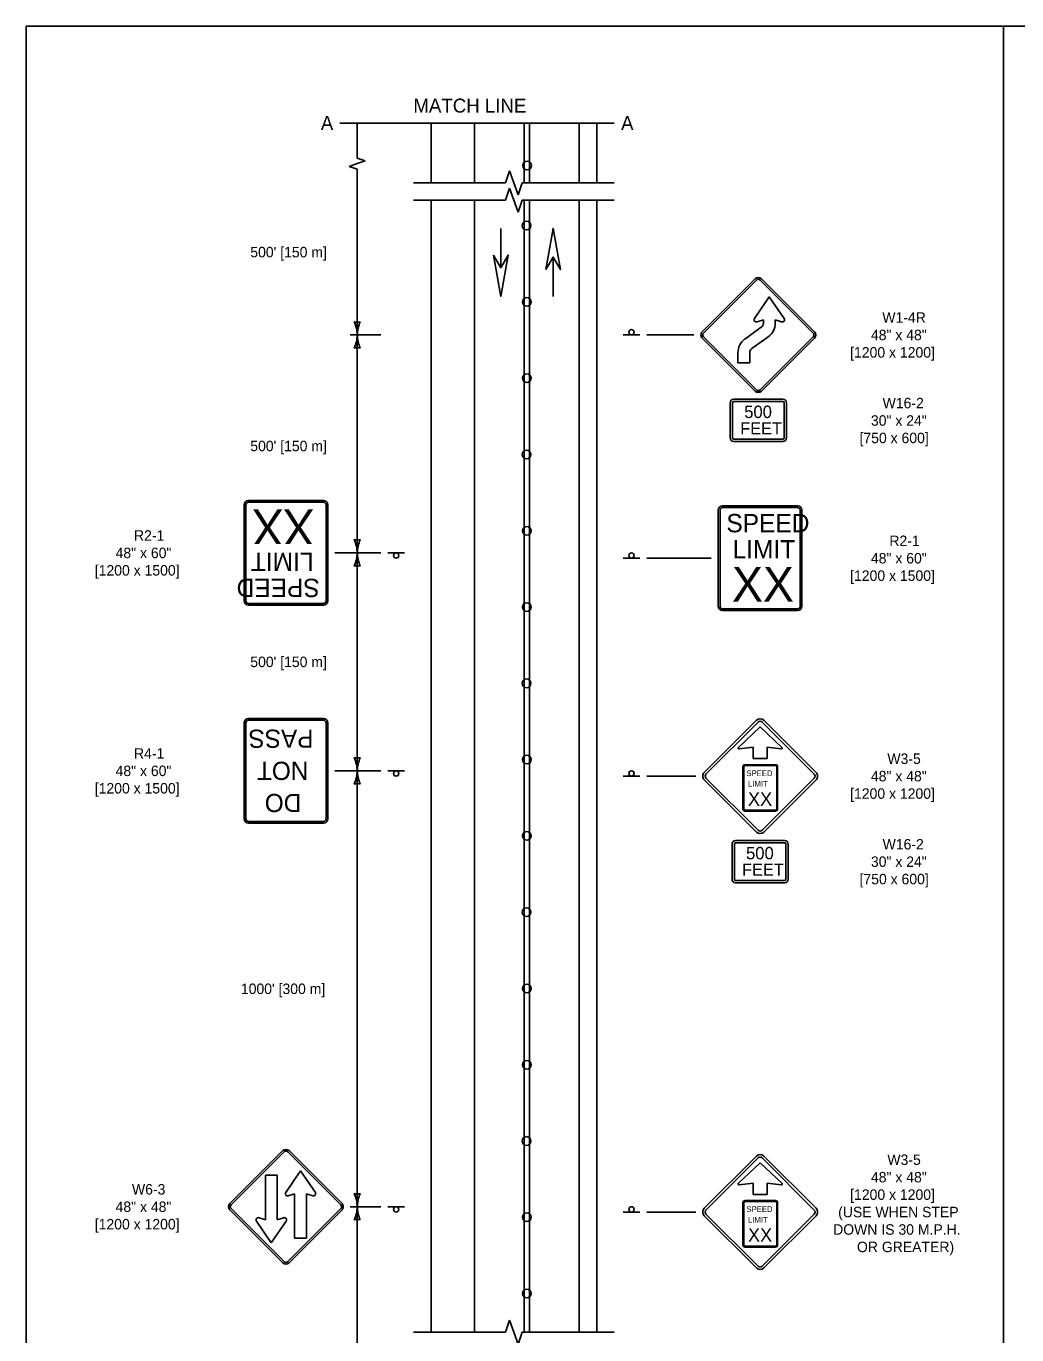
# Model space of a CAD drawing. Extents: x 49991.4 to 50021, y 49987.6 to 50011.4.
# Drawn here: x 49999.38 to 50005.06, y 49991.49 to 49999 of the extents above; entities that cross this region are included whole.
import ezdxf

# ---------------------------------------------------------------- set-up
doc = ezdxf.new("R2010")
doc.units = 0
for name, color, linetype in [('Level 1', 7, 'Continuous'), ('Level 2', 7, 'Continuous'), ('Level 3', 7, 'Continuous'), ('Level 6', 7, 'Continuous')]:
    doc.layers.add(name, color=color, linetype=linetype)

msp = doc.modelspace()

# ---------------------------------------------------------------- linework, layer by layer
at = {"layer": 'Level 1'}
for p, q in [((50001.7052, 49998.1012), (50001.7052, 49998.4436)), ((50001.9552, 49998.1012), (50001.9552, 49998.4436)), ((50002.2402, 49998.1012), (50002.2402, 49998.4436)), ((50002.2702, 49998.1012), (50002.2702, 49998.4436)), ((50002.5552, 49998.1012), (50002.5552, 49998.4436)), ((50002.6552, 49998.1012), (50002.6552, 49998.4436)), ((50001.7052, 49991.5092), (50001.7052, 49998.0012)), ((50001.9552, 49991.5092), (50001.9552, 49998.0012)), ((50002.2402, 49991.5092), (50002.2402, 49998.0012)), ((50002.2702, 49991.5092), (50002.2702, 49998.0012)), ((50002.5552, 49991.5092), (50002.5552, 49998.0012)), ((50002.6552, 49991.5092), (50002.6552, 49998.0012)), ((50002.1052, 49997.8396), (50002.1052, 49997.6138)), ((50002.1054, 49997.8396), (50002.1054, 49997.6138)), ((50002.4051, 49997.4496), (50002.4051, 49997.6754)), ((50002.4053, 49997.4496), (50002.4053, 49997.6754)), ((50003.2604, 49997.2459), (50003.5645, 49997.5499)), ((50003.2675, 49997.2388), (50003.5715, 49997.5429)), ((50003.5927, 49997.5429), (50003.8968, 49997.2388)), ((50003.5998, 49997.5499), (50003.9039, 49997.2459)), ((50003.6452, 49997.4466), (50003.5602, 49997.3229)), ((50003.7304, 49997.3229), (50003.6452, 49997.4466)), ((50003.5748, 49997.3032), (50003.6113, 49997.315)), ((50003.6113, 49997.315), (50003.6113, 49997.2962)), ((50003.6792, 49997.2962), (50003.6792, 49997.315)), ((50003.6792, 49997.315), (50003.7157, 49997.3032)), ((50002.8071, 49997.2283), (50002.9031, 49997.2283)), ((50003.5992, 49997.2725), (50003.5056, 49997.205)), ((50003.5645, 49996.9065), (50003.2604, 49997.2105)), ((50003.5715, 49996.9135), (50003.2675, 49997.2176)), ((50003.5453, 49997.1498), (50003.6389, 49997.2174)), ((50003.8968, 49997.2176), (50003.5927, 49996.9135)), ((50003.9039, 49997.2105), (50003.5998, 49996.9065)), ((50003.4653, 49997.1263), (50003.4653, 49997.068)), ((50003.5332, 49997.068), (50003.5332, 49997.1263)), ((50003.4653, 49997.068), (50003.5332, 49997.068)), ((50003.441, 49996.8592), (50003.7233, 49996.8592)), ((50003.4209, 49996.6375), (50003.4209, 49996.8391)), ((50003.4343, 49996.8391), (50003.4343, 49996.6375)), ((50003.7233, 49996.8458), (50003.441, 49996.8458)), ((50003.73, 49996.6375), (50003.73, 49996.8391)), ((50003.7434, 49996.8391), (50003.7434, 49996.6375)), ((50003.441, 49996.6308), (50003.7233, 49996.6308)), ((50003.7233, 49996.6173), (50003.441, 49996.6173)), ((50000.6331, 49995.7033), (50000.6331, 49996.2533)), ((50000.6431, 49995.7033), (50000.6431, 49996.2533)), ((50000.6581, 49996.2783), (50001.0881, 49996.2783)), ((50000.6581, 49996.2683), (50001.0881, 49996.2683)), ((50001.1031, 49996.2533), (50001.1031, 49995.7033)), ((50001.1131, 49996.2533), (50001.1131, 49995.7033)), ((50003.3527, 49995.6728), (50003.3527, 49996.2228)), ((50003.3627, 49995.6728), (50003.3627, 49996.2228)), ((50003.3777, 49996.2478), (50003.8077, 49996.2478)), ((50003.3777, 49996.2378), (50003.8077, 49996.2378)), ((50003.8227, 49996.2228), (50003.8227, 49995.6728)), ((50003.8327, 49996.2228), (50003.8327, 49995.6728)), ((50001.5532, 49995.9783), (50001.4572, 49995.9783)), ((50002.8071, 49995.9478), (50002.9031, 49995.9478)), ((50001.0881, 49995.6883), (50000.6581, 49995.6883)), ((50001.0881, 49995.6783), (50000.6581, 49995.6783)), ((50003.8077, 49995.6578), (50003.3777, 49995.6578)), ((50003.8077, 49995.6478), (50003.3777, 49995.6478)), ((50000.6331, 49994.4533), (50000.6331, 49995.0033)), ((50000.6431, 49994.4533), (50000.6431, 49995.0033)), ((50000.6581, 49995.0281), (50001.0881, 49995.0281)), ((50000.6581, 49995.0181), (50001.0881, 49995.0181)), ((50001.1031, 49995.0033), (50001.1031, 49994.4533)), ((50001.1131, 49995.0033), (50001.1131, 49994.4533)), ((50003.272, 49994.7192), (50003.5713, 49995.0185)), ((50003.2821, 49994.7091), (50003.5814, 49995.0084)), ((50003.4683, 49994.8628), (50003.5927, 49994.9801)), ((50003.5927, 49994.9801), (50003.7171, 49994.8628)), ((50003.604, 49995.0084), (50003.9033, 49994.7091)), ((50003.604, 49995.0084), (50003.604, 49995.0084)), ((50003.6141, 49995.0185), (50003.9134, 49994.7192)), ((50003.6141, 49995.0185), (50003.6141, 49995.0185)), ((50003.5524, 49994.8642), (50003.4724, 49994.8541)), ((50003.5524, 49994.7987), (50003.5524, 49994.8642)), ((50003.633, 49994.8642), (50003.633, 49994.7987)), ((50003.7131, 49994.8541), (50003.633, 49994.8642)), ((50003.4934, 49994.7511), (50003.4934, 49994.5098)), ((50003.4986, 49994.7511), (50003.4986, 49994.5098)), ((50003.6806, 49994.7636), (50003.5059, 49994.7636)), ((50003.6806, 49994.7584), (50003.5059, 49994.7584)), ((50003.633, 49994.7987), (50003.5524, 49994.7987)), ((50003.5932, 49994.7636), (50003.5932, 49994.7636)), ((50003.6879, 49994.5098), (50003.6879, 49994.7511)), ((50003.6931, 49994.5098), (50003.6931, 49994.7511)), ((50001.5532, 49994.7283), (50001.4572, 49994.7283)), ((50002.8071, 49994.6979), (50002.9031, 49994.6979)), ((50003.5713, 49994.3772), (50003.272, 49994.6765)), ((50003.5814, 49994.3873), (50003.2821, 49994.6866)), ((50003.9033, 49994.6866), (50003.604, 49994.3873)), ((50003.9134, 49994.6765), (50003.6141, 49994.3772)), ((50003.5059, 49994.5025), (50003.6806, 49994.5025)), ((50003.5059, 49994.4973), (50003.6806, 49994.4973)), ((50001.0881, 49994.4381), (50000.6581, 49994.4381)), ((50001.0881, 49994.4281), (50000.6581, 49994.4281)), ((50003.4314, 49994.1066), (50003.4314, 49994.3082)), ((50003.4449, 49994.3082), (50003.4449, 49994.1066)), ((50003.4516, 49994.3283), (50003.7338, 49994.3283)), ((50003.7338, 49994.3149), (50003.4516, 49994.3149)), ((50003.7406, 49994.1066), (50003.7406, 49994.3082)), ((50003.754, 49994.3082), (50003.754, 49994.1066)), ((50003.4516, 49994.0998), (50003.7338, 49994.0998)), ((50003.7338, 49994.0864), (50003.4516, 49994.0864)), ((50000.5513, 49992.2459), (50000.8555, 49992.5499)), ((50000.5585, 49992.2387), (50000.8625, 49992.5429)), ((50000.8837, 49992.5429), (50001.1877, 49992.2387)), ((50000.8909, 49992.5499), (50001.1949, 49992.2459)), ((50003.272, 49992.2192), (50003.5713, 49992.5185)), ((50003.2821, 49992.2091), (50003.5814, 49992.5084)), ((50003.604, 49992.5084), (50003.9033, 49992.2091)), ((50003.604, 49992.5084), (50003.604, 49992.5084)), ((50003.6141, 49992.5185), (50003.9134, 49992.2192)), ((50003.6141, 49992.5185), (50003.6141, 49992.5185)), ((50000.8717, 49992.3107), (50000.9569, 49992.4345)), ((50000.9569, 49992.4345), (50001.0421, 49992.3107)), ((50003.4683, 49992.3628), (50003.5927, 49992.4801)), ((50003.5927, 49992.4801), (50003.7171, 49992.3628)), ((50000.7553, 49992.4089), (50000.8233, 49992.4089)), ((50000.7553, 49992.1535), (50000.7553, 49992.4089)), ((50000.8233, 49992.4089), (50000.8233, 49992.1535)), ((50003.5524, 49992.3641), (50003.4724, 49992.3541)), ((50003.5524, 49992.2986), (50003.5524, 49992.3641)), ((50003.633, 49992.3641), (50003.633, 49992.2986)), ((50003.7131, 49992.3541), (50003.633, 49992.3641)), ((50000.9229, 49992.3031), (50000.8865, 49992.2911)), ((50000.9229, 49992.0475), (50000.9229, 49992.3031)), ((50001.0273, 49992.2911), (50000.9909, 49992.3031)), ((50000.9909, 49992.3031), (50000.9909, 49992.0475)), ((50003.633, 49992.2986), (50003.5524, 49992.2986)), ((50000.8555, 49991.9065), (50000.5513, 49992.2105)), ((50000.8625, 49991.9135), (50000.5585, 49992.2175)), ((50001.1877, 49992.2175), (50000.8837, 49991.9135)), ((50001.1949, 49992.2105), (50000.8909, 49991.9065)), ((50001.5532, 49992.2283), (50001.4572, 49992.2283)), ((50003.4934, 49992.2511), (50003.4934, 49992.0098)), ((50003.4986, 49992.2511), (50003.4986, 49992.0098)), ((50003.6806, 49992.2635), (50003.5059, 49992.2635)), ((50003.6806, 49992.2583), (50003.5059, 49992.2583)), ((50003.5932, 49992.2635), (50003.5932, 49992.2635)), ((50003.6879, 49992.0098), (50003.6879, 49992.2511)), ((50003.6931, 49992.0098), (50003.6931, 49992.2511)), ((50000.7893, 49992.0219), (50000.7043, 49992.1455)), ((50000.7189, 49992.1651), (50000.7553, 49992.1535)), ((50000.8745, 49992.1455), (50000.7893, 49992.0219)), ((50000.8233, 49992.1535), (50000.8597, 49992.1651)), ((50002.8071, 49992.1978), (50002.9031, 49992.1978)), ((50003.5713, 49991.8771), (50003.272, 49992.1764)), ((50003.5814, 49991.8872), (50003.2821, 49992.1865)), ((50003.9033, 49992.1865), (50003.604, 49991.8872)), ((50003.9134, 49992.1764), (50003.6141, 49991.8771)), ((50000.9909, 49992.0475), (50000.9229, 49992.0475)), ((50003.5059, 49992.0025), (50003.6806, 49992.0025)), ((50003.5059, 49991.9973), (50003.6806, 49991.9973))]:
    msp.add_line(p, q, dxfattribs=at)
for points in [[(49999.3835, 49998.9992), (50016.7501, 49998.9992), (50016.7501, 49987.7988), (49999.3835, 49987.7988)], [(50002.3633, 49997.6032), (50002.4051, 49997.8396), (50002.4469, 49997.6032), (50002.4051, 49997.6752)], [(50002.0634, 49997.686), (50002.1052, 49997.4496), (50002.147, 49997.686), (50002.1052, 49997.614)]]:
    msp.add_lwpolyline(points, close=True, dxfattribs=at)
for centre, radius in [((50002.2561, 49998.1995), 0.025), ((50002.2524, 49997.8552), 0.025), ((50002.255, 49997.4177), 0.025), ((50002.855, 49997.2436), 0.0152), ((50002.255, 49996.9802), 0.025), ((50002.255, 49996.9802), 0.025), ((50002.2524, 49996.5427), 0.025), ((50002.255, 49996.1052), 0.025), ((50001.5052, 49995.9631), 0.0152), ((50002.855, 49995.9631), 0.0152), ((50002.255, 49995.6677), 0.025), ((50002.255, 49995.6677), 0.025), ((50002.2524, 49995.2302), 0.025), ((50002.255, 49994.7927), 0.025), ((50001.5052, 49994.7131), 0.0152), ((50002.855, 49994.7132), 0.0152), ((50002.255, 49994.3552), 0.025), ((50002.255, 49994.3552), 0.025), ((50002.2524, 49993.9177), 0.025), ((50002.255, 49993.4802), 0.025), ((50002.255, 49993.0427), 0.025), ((50002.255, 49993.0427), 0.025), ((50002.2524, 49992.6052), 0.025), ((50001.5052, 49992.2131), 0.0152), ((50002.855, 49992.2131), 0.0152), ((50002.255, 49992.1677), 0.025), ((50002.255, 49991.7302), 0.025)]:
    msp.add_circle(centre, radius, dxfattribs=at)
for centre, radius, start, end in [((50003.5821, 49997.5324), 0.025, 45, 135), ((50003.5821, 49997.5324), 0.015, 45, 135), ((50003.5708, 49997.3157), 0.0129, 145.48059, 287.95818), ((50003.7197, 49997.3157), 0.0129, 252.04182, 34.51941), ((50003.2781, 49997.2283), 0.025, 134.99976, 225), ((50003.2781, 49997.2283), 0.015, 134.99976, 225), ((50003.5821, 49997.2962), 0.0291, 305.79716, 0), ((50003.5821, 49997.2962), 0.0971, 305.79716, 0), ((50003.8862, 49997.2283), 0.015, 315, 45), ((50003.8862, 49997.2283), 0.025, 315, 45), ((50003.5623, 49997.1264), 0.0971, 125.79716, 180), ((50003.5623, 49997.1264), 0.0291, 125.79744, 180), ((50003.441, 49996.8391), 0.0202, 90, 180), ((50003.5821, 49996.9242), 0.025, 225.00043, 315), ((50003.5821, 49996.9242), 0.015, 225.00043, 315), ((50003.7233, 49996.8391), 0.0202, 0, 90), ((50003.441, 49996.8391), 0.00672, 90, 180), ((50003.7233, 49996.8391), 0.00672, 0, 90), ((50003.441, 49996.6375), 0.0202, 180, 270), ((50003.441, 49996.6375), 0.00672, 180, 270), ((50003.7233, 49996.6375), 0.00672, 270, 0), ((50003.7233, 49996.6375), 0.0202, 270, 0), ((50000.6581, 49996.2533), 0.025, 90, 180), ((50000.6581, 49996.2533), 0.015, 90, 180), ((50001.0881, 49996.2533), 0.025, 0, 90), ((50001.0881, 49996.2533), 0.015, 0, 90), ((50003.3777, 49996.2228), 0.025, 90, 180), ((50003.3777, 49996.2228), 0.015, 90, 180), ((50003.8077, 49996.2228), 0.025, 0, 90), ((50003.8077, 49996.2228), 0.015, 0, 90), ((50000.6581, 49995.7033), 0.025, 180, 270), ((50000.6581, 49995.7033), 0.015, 180, 270), ((50001.0881, 49995.7033), 0.025, 270, 0), ((50001.0881, 49995.7033), 0.015, 270, 0), ((50003.3777, 49995.6728), 0.025, 180, 270), ((50003.3777, 49995.6728), 0.015, 180, 270), ((50003.8077, 49995.6728), 0.025, 270, 0), ((50003.8077, 49995.6728), 0.015, 270, 0), ((50000.6581, 49995.0033), 0.025, 90, 180), ((50000.6581, 49995.0033), 0.015, 90, 180), ((50001.0881, 49995.0033), 0.025, 0, 90), ((50001.0881, 49995.0033), 0.015, 0, 90), ((50003.5927, 49994.9972), 0.0302, 45.00007, 134.99993), ((50003.5927, 49994.9972), 0.016, 45.00007, 134.99993), ((50003.4719, 49994.8592), 0.00509, 134.83509, 275.61741), ((50003.7136, 49994.8592), 0.00508, 264.17053, 45.37126), ((50003.5059, 49994.7511), 0.0125, 90, 180), ((50003.5059, 49994.7511), 0.00728, 90, 180), ((50003.6806, 49994.7511), 0.0125, 0, 90), ((50003.6806, 49994.7511), 0.00728, 0, 90), ((50003.2934, 49994.6979), 0.0302, 134.99992, 225.00007), ((50003.2934, 49994.6979), 0.016, 134.99993, 225.00007), ((50003.892, 49994.6979), 0.016, 314.99992, 45.00007), ((50003.892, 49994.6979), 0.0302, 314.99992, 45.00007), ((50000.6581, 49994.4533), 0.025, 180, 270), ((50000.6581, 49994.4533), 0.015, 180, 270), ((50001.0881, 49994.4533), 0.025, 270, 0), ((50001.0881, 49994.4533), 0.015, 270, 0), ((50003.5059, 49994.5098), 0.0125, 180, 270), ((50003.5059, 49994.5098), 0.00728, 180, 270), ((50003.6806, 49994.5098), 0.00728, 270, 0), ((50003.6806, 49994.5098), 0.0125, 270, 0), ((50003.5927, 49994.3986), 0.0302, 225.00007, 314.99993), ((50003.5927, 49994.3986), 0.016, 225.00007, 314.99993), ((50003.4516, 49994.3082), 0.0202, 90, 180), ((50003.4516, 49994.3082), 0.00672, 90, 180), ((50003.7338, 49994.3082), 0.0202, 0, 90), ((50003.7338, 49994.3082), 0.00672, 0, 90), ((50003.4516, 49994.1066), 0.0202, 180, 270), ((50003.4516, 49994.1066), 0.00672, 180, 270), ((50003.7338, 49994.1066), 0.00672, 270, 0), ((50003.7338, 49994.1066), 0.0202, 270, 0), ((50000.8731, 49992.5324), 0.025, 45.00043, 135), ((50000.8731, 49992.5324), 0.015, 45.00043, 135), ((50003.5927, 49992.4971), 0.0302, 45.00007, 134.99993), ((50003.5927, 49992.4971), 0.016, 45.00007, 134.99993), ((50003.4719, 49992.3591), 0.00509, 134.83509, 275.61741), ((50003.7136, 49992.3591), 0.00508, 264.17053, 45.37126), ((50000.8825, 49992.3036), 0.0129, 145.58495, 216.71634), ((50000.8825, 49992.3036), 0.0129, 216.71939, 287.95818), ((50001.0313, 49992.3036), 0.0129, 252.04182, 323.27756), ((50001.0313, 49992.3036), 0.0129, 323.28061, 34.51941), ((50000.5691, 49992.2283), 0.025, 135, 225), ((50000.5691, 49992.2283), 0.015, 135, 225), ((50001.1772, 49992.2283), 0.015, 314.99976, 45), ((50001.1772, 49992.2283), 0.025, 314.99976, 45), ((50003.2934, 49992.1978), 0.0302, 134.99992, 225.00007), ((50003.2934, 49992.1978), 0.016, 134.99993, 225.00007), ((50003.5059, 49992.2511), 0.0125, 90, 180), ((50003.5059, 49992.2511), 0.00728, 90, 180), ((50003.6806, 49992.2511), 0.0125, 0, 90), ((50003.6806, 49992.2511), 0.00728, 0, 90), ((50003.892, 49992.1978), 0.016, 314.99992, 45.00007), ((50003.892, 49992.1978), 0.0302, 314.99992, 45.00007), ((50000.7149, 49992.153), 0.0129, 143.28061, 214.51941), ((50000.7149, 49992.153), 0.0129, 72.04182, 143.27756), ((50000.8638, 49992.153), 0.0129, 36.71939, 107.95818), ((50000.8638, 49992.153), 0.0129, 325.58495, 36.71634), ((50003.5059, 49992.0098), 0.0125, 180, 270), ((50003.5059, 49992.0098), 0.00728, 180, 270), ((50003.6806, 49992.0098), 0.00728, 270, 0), ((50003.6806, 49992.0098), 0.0125, 270, 0), ((50000.8731, 49991.9242), 0.025, 225, 315), ((50000.8731, 49991.9242), 0.015, 225, 315), ((50003.5927, 49991.8985), 0.0302, 225.00007, 314.99993), ((50003.5927, 49991.8985), 0.016, 225.00007, 314.99993)]:
    msp.add_arc(centre, radius, start, end, dxfattribs=at)
at = {"layer": 'Level 3'}
for p, q in [((50004.9877, 49987.7988), (50004.9877, 49998.9992)), ((50001.2822, 49998.2431), (50001.2822, 49998.4436)), ((50001.2365, 49998.1945), (50001.2822, 49998.2107)), ((50001.2822, 49998.2431), (50001.3279, 49998.2269)), ((50001.2822, 49998.2107), (50001.3279, 49998.2269)), ((50001.2365, 49998.1945), (50001.2822, 49998.1783)), ((50001.2822, 49998.1783), (50001.2822, 49997.2283)), ((50001.2422, 49997.2283), (50001.4172, 49997.2283)), ((50001.2822, 49997.2283), (50001.2822, 49995.9546)), ((50003.2131, 49997.2283), (50002.9431, 49997.2283)), ((50001.1531, 49995.9783), (50001.4172, 49995.9783)), ((50001.2822, 49994.7283), (50001.2822, 49995.9783)), ((50003.3127, 49995.9478), (50002.9431, 49995.9478)), ((50001.1531, 49994.7283), (50001.4172, 49994.7283)), ((50001.2822, 49992.2283), (50001.2822, 49994.7283)), ((50003.2232, 49994.6979), (50002.9431, 49994.6979)), ((50001.2422, 49992.2283), (50001.4172, 49992.2283)), ((50001.2822, 49992.2283), (50001.2822, 49991.3619)), ((50002.9431, 49992.1978), (50003.2232, 49992.1978))]:
    msp.add_line(p, q, dxfattribs=at)
for centre, radius, start, end in [((50001.2822, 49997.3565), 0.0548, 252.13882, 287.86118), ((50001.0495, 49997.2168), 0.233, 2.82731, 22.07716), ((50001.5043, 49997.2191), 0.2223, 157.45601, 177.63952), ((50001.0601, 49997.2375), 0.2223, 337.45601, 357.63952), ((50001.5149, 49997.2398), 0.233, 182.82731, 202.07716), ((50001.2822, 49997.1001), 0.0548, 72.13882, 107.86118), ((50001.2822, 49996.1065), 0.0548, 252.13882, 287.86118), ((50001.0495, 49995.9668), 0.233, 2.82731, 22.07716), ((50001.5043, 49995.9691), 0.2223, 157.45601, 177.63952), ((50001.0601, 49995.9875), 0.2223, 337.45601, 357.63952), ((50001.5149, 49995.9898), 0.233, 182.82731, 202.07716), ((50001.2822, 49995.8501), 0.0548, 72.13882, 107.86118), ((50001.2822, 49994.8565), 0.0548, 252.13882, 287.86118), ((50001.0495, 49994.7168), 0.233, 2.82731, 22.07716), ((50001.5043, 49994.7191), 0.2223, 157.45601, 177.63952), ((50001.0601, 49994.7375), 0.2223, 337.45601, 357.63952), ((50001.5149, 49994.7398), 0.233, 182.82731, 202.07716), ((50001.2822, 49994.6001), 0.0548, 72.13882, 107.86118), ((50001.2822, 49992.3565), 0.0548, 252.13882, 287.86118), ((50001.0495, 49992.2168), 0.233, 2.82731, 22.07716), ((50001.5043, 49992.2191), 0.2223, 157.45601, 177.63952), ((50001.0601, 49992.2375), 0.2223, 337.45601, 357.63952), ((50001.5149, 49992.2398), 0.233, 182.82731, 202.07716), ((50001.2822, 49992.1001), 0.0548, 72.13882, 107.86118)]:
    msp.add_arc(centre, radius, start, end, dxfattribs=at)
at = {"layer": 'Level 6'}
for p, q in [((50002.7552, 49998.4436), (50001.1822, 49998.4436)), ((50002.1316, 49998.1012), (50002.156, 49998.17)), ((50002.1802, 49998.1012), (50002.156, 49998.17)), ((50002.1316, 49998.1012), (50001.6052, 49998.1012)), ((50002.1316, 49998.0012), (50002.156, 49998.07)), ((50002.1802, 49998.0012), (50002.156, 49998.07)), ((50002.2044, 49998.0328), (50002.1802, 49998.1012)), ((50002.2044, 49998.0328), (50002.2288, 49998.1012)), ((50002.7552, 49998.1012), (50002.2288, 49998.1012)), ((50002.1316, 49998.0012), (50001.6052, 49998.0012)), ((50002.2044, 49997.9328), (50002.1802, 49998.0012)), ((50002.2044, 49997.9328), (50002.2288, 49998.0012)), ((50002.7552, 49998.0012), (50002.2288, 49998.0012)), ((50002.1316, 49991.5092), (50002.156, 49991.578)), ((50002.1802, 49991.5092), (50002.156, 49991.578)), ((50002.1316, 49991.5092), (50001.6052, 49991.5092)), ((50002.2044, 49991.4408), (50002.1802, 49991.5092)), ((50002.2044, 49991.4408), (50002.2288, 49991.5092)), ((50002.7552, 49991.5092), (50002.2288, 49991.5092))]:
    msp.add_line(p, q, dxfattribs=at)

# ---------------------------------------------------------------- texts
at = {"layer": 'Level 1'}
for s, height, rotation, p in [('500', 0.07124, 360, (50003.5012, 49996.7517)), ('FEET', 0.06989, 360, (50003.4789, 49996.6576)), ('XX', 0.1989, 180, (50001.0347, 49996.2274)), ('LIMIT', 0.10512, 180, (50001.0315, 49995.9801)), ('SPEED', 0.10512, 180, (50001.0669, 49995.83)), ('PASS', 0.1044, 180, (50001.0312, 49994.9649)), ('NOT', 0.1044, 180, (50001.0018, 49994.7805)), ('DO', 0.1044, 180, (50000.9611, 49994.5961)), ('500', 0.07124, 360, (50003.5118, 49994.2208)), ('FEET', 0.06989, 360, (50003.4895, 49994.1267))]:
    msp.add_text(s, height=height, rotation=rotation, dxfattribs=at).set_placement(p)
for s, height, p in [('SPEED', 0.10512, (50003.399, 49996.0964)), ('LIMIT', 0.10512, (50003.4345, 49995.9462)), ('XX', 0.19892, (50003.4313, 49995.699)), ('SPEED', 0.03301, (50003.514, 49994.6979)), ('XX', 0.07775, (50003.5229, 49994.5275)), ('LIMIT', 0.03301, (50003.5231, 49994.6369)), ('SPEED', 0.03301, (50003.514, 49992.1978)), ('LIMIT', 0.03301, (50003.5231, 49992.1368)), ('XX', 0.07775, (50003.5229, 49992.0274))]:
    msp.add_text(s, height=height, dxfattribs=at).set_placement(p)
at = {"layer": 'Level 2'}
for s, height, p in [('MATCH LINE', 0.08, (50001.6041, 49998.5036)), ('A', 0.08, (50001.0735, 49998.4036)), ('A', 0.08, (50002.7952, 49998.4036)), ("500' [150 m]", 0.06, (50000.6688, 49997.6733)), ('W1-4R', 0.06, (50004.2932, 49997.2983)), ('48" x 48"', 0.06, (50004.2281, 49997.1983)), ('[1200 x 1200]', 0.06, (50004.1087, 49997.0983)), ('W16-2', 0.06, (50004.295, 49996.8076)), ('30" x 24"', 0.06, (50004.2281, 49996.7076)), ('[750 x 600]', 0.06, (50004.1625, 49996.6076)), ("500' [150 m]", 0.06, (50000.6688, 49996.5614)), ('R2-1', 0.06, (50000.0019, 49996.0483)), ('R2-1', 0.06, (50004.3337, 49996.0178)), ('48" x 60"', 0.06, (49999.8963, 49995.9483)), ('48" x 60"', 0.06, (50004.2281, 49995.9178)), ('[1200 x 1500]', 0.06, (49999.7769, 49995.8483)), ('[1200 x 1500]', 0.06, (50004.1087, 49995.8178)), ("500' [150 m]", 0.06, (50000.6688, 49995.3233)), ('R4-1', 0.06, (50000.0019, 49994.7983)), ('W3-5', 0.05999, (50004.3222, 49994.7678)), ('48" x 60"', 0.06, (49999.8963, 49994.6983)), ('48" x 48"', 0.05999, (50004.2281, 49994.6679)), ('[1200 x 1500]', 0.06, (49999.7769, 49994.5983)), ('[1200 x 1200]', 0.059993, (50004.1087, 49994.568)), ('W16-2', 0.05999, (50004.295, 49994.2773)), ('30" x 24"', 0.05999, (50004.2281, 49994.1774)), ('[750 x 600]', 0.059993, (50004.1626, 49994.0775)), ("1000' [300 m]", 0.06, (50000.6149, 49993.4483)), ('W3-5', 0.06, (50004.3223, 49992.4678)), ('48" x 48"', 0.06, (50004.2282, 49992.3678)), ('W6-3', 0.06, (49999.9901, 49992.2983)), ('[1200 x 1200]', 0.06, (50004.1088, 49992.2678)), ('48" x 48"', 0.06, (49999.8963, 49992.1983)), ('(USE WHEN STEP', 0.06, (50004.0401, 49992.1678)), ('[1200 x 1200]', 0.06, (49999.7769, 49992.0983)), ('DOWN IS 30 M.P.H.', 0.06, (50004.0113, 49992.0678)), ('OR GREATER)', 0.06, (50004.148, 49991.9678))]:
    msp.add_text(s, height=height, dxfattribs=at).set_placement(p)

doc.saveas('drawing.dxf')
